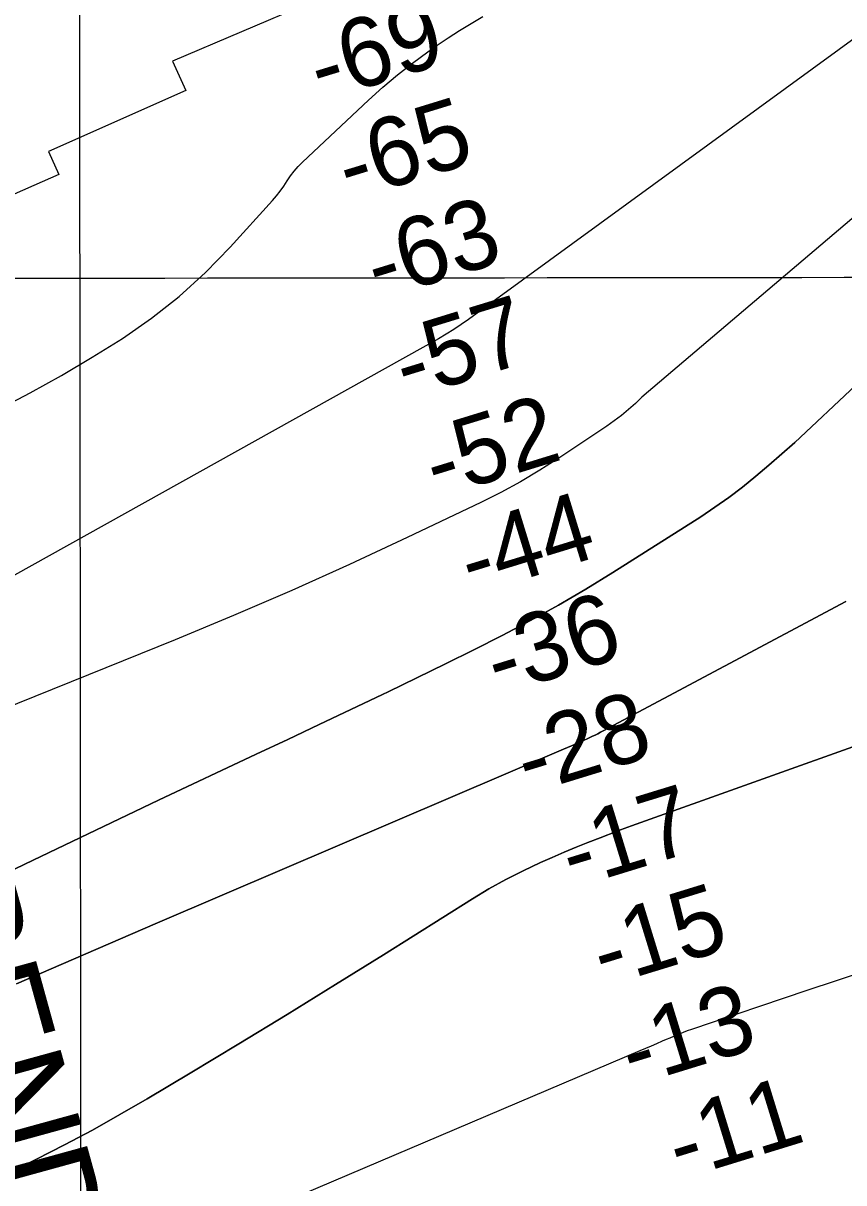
# Model space of a CAD drawing. Extents: x 3297753 to 3335611, y 652252 to 677623.
# Drawn here: x 3317590 to 3318384, y 659798 to 660921 of the extents above; entities that cross this region are included whole.
import ezdxf

# ---------------------------------------------------------------- set-up
doc = ezdxf.new("R2010")
doc.units = 0
for name, color, linetype in [('V-CHAN-NAID', 7, 'Continuous'), ('V-GRID-MAJR', 7, 'Continuous'), ('V-RIVR-EDGE', 7, 'Continuous'), ('V-RIVR-RANG', 7, 'Continuous'), ('V-RRAP-FSHR', 7, 'Continuous'), ('V-RRAP-RVMT', 7, 'Continuous'), ('V-TOPO-DPTH', 7, 'Continuous'), ('V-TOPO-MAJR', 7, 'Continuous'), ('V-TOPO-MINR', 7, 'Continuous')]:
    doc.layers.add(name, color=color, linetype=linetype)

msp = doc.modelspace()

# ---------------------------------------------------------------- linework, layer by layer
at = {"layer": 'V-GRID-MAJR'}
for points in [[(3317647.879, 657646.666), (3317644.7970000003, 660673.924), (3317638.625, 666735.341), (3317632.454, 672796.784), (3317629.365, 675830.954)], [(3301868.458, 660661.303), (3307127.238, 660664.745), (3312386.018, 660668.952), (3317644.7970000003, 660673.924), (3322903.575, 660679.66), (3328162.353, 660686.162), (3333421.129, 660693.428), (3333421.13, 660693.428)]]:
    msp.add_spline(points, degree=3, dxfattribs=at)
at = {"layer": 'V-RIVR-EDGE'}
msp.add_spline([(3319472.941637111, 662096.7930483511), (3319451.3588761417, 662084.8263787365), (3319431.435066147, 662073.2700910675), (3319412.763924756, 662065.4410623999), (3319386.63724047, 662059.7028894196), (3319355.1274208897, 662056.0504476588), (3319321.5328949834, 662047.4293521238), (3319286.6877502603, 662035.909960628), (3319261.790162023, 662024.3659716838), (3319253.9098886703, 662022.3130370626), (3319243.962332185, 662022.3376345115), (3319236.9110218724, 662020.2826501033), (3319220.298964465, 662007.0602372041), (3319214.062268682, 661999.2004617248), (3319197.881091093, 661992.6087282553), (3319174.651677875, 661985.2054549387), (3319135.249286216, 661974.5263003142), (3319095.8438198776, 661962.603701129), (3319061.8266133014, 661950.6677783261), (3319035.6896800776, 661940.7847901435), (3319017.017513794, 661932.5412799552), (3319004.1501385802, 661925.1123842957), (3318977.5966740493, 661914.4014579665), (3318949.3975821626, 661908.6684094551), (3318929.074664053, 661903.3303694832), (3318893.4067056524, 661894.2999168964), (3318836.1693099, 661878.6910544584), (3318802.1592775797, 661869.6565022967), (3318784.3232485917, 661864.3123129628), (3318761.0999847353, 661859.3959287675), (3318735.3744583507, 661848.2684711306), (3318707.1599930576, 661836.3181998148), (3318683.937754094, 661831.8162971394), (3318667.767850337, 661829.7838603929), (3318647.8604386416, 661824.8592770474), (3318612.1842810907, 661812.5129722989), (3318583.557384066, 661801.3926889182), (3318550.7836220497, 661789.4536914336), (3318517.189096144, 661780.8325958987), (3318486.906322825, 661770.5453751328), (3318459.104289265, 661757.7651158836), (3318437.1142210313, 661748.7008418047), (3318401.0928960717, 661732.5599758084), (3318376.26750918, 661719.6611275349), (3318350.3290856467, 661712.3999159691), (3318322.694633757, 661702.8889443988), (3318295.6167001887, 661690.5591544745), (3318275.8849717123, 661686.6635262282), (3318257.8395182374, 661681.0732629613), (3318243.7328864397, 661673.2193063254), (3318214.402406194, 661661.4585747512), (3318180.554292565, 661645.7645948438), (3318148.3966339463, 661630.066434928), (3318131.4656104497, 661619.4020199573), (3318111.1439235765, 661604.8015699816), (3318079.514916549, 661575.0148916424), (3318056.375804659, 661560.4214083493), (3318032.664847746, 661542.4484083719), (3318016.2987025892, 661532.346085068), (3317961.5347636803, 661489.6563784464), (3317862.7409676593, 661415.5201918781), (3317830.000317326, 661391.9346352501), (3317829.4284723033, 661388.5551185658), (3317827.160598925, 661382.925841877), (3317810.80142045, 661375.6409435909), (3317785.9690668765, 661359.9246703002), (3317761.132533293, 661342.5179419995), (3317743.6157314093, 661322.83916031), (3317726.093356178, 661300.9064386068), (3317708.570980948, 661278.9737169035), (3317696.7168958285, 661270.5507019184), (3317673.576390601, 661255.3937336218), (3317601.3165498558, 661201.4775203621), (3317560.671782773, 661171.7131354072), (3317529.070642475, 661153.1961571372), (3317513.8245006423, 661140.2736221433), (3317483.9026686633, 661117.2445838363), (3317464.1514334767, 661105.4601655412), (3317423.524779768, 661083.0210856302), (3317409.427901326, 661079.1115240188), (3317401.539111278, 661079.1310307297), (3317375.02187604, 661065.6728774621), (3317364.298940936, 661058.9375308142), (3317348.501854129, 661051.0877541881), (3317330.4591873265, 661046.6244609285), (3317307.322862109, 661033.1579476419), (3317289.2704419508, 661024.7502593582), (3317263.8829633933, 661012.4162894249), (3317240.770324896, 661008.5290211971), (3317230.0529631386, 661004.047614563), (3317228.3527547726, 661000.107399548), (3317221.5867547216, 660998.4336645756), (3317196.2118161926, 660991.1710596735), (3317170.2678193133, 660981.6559080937), (3317149.4105141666, 660978.3265515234), (3317103.1615504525, 660960.9727700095), (3317073.2689785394, 660949.7769167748), (3317034.3383531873, 660929.5875968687), (3316995.9726061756, 660909.9603686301), (3316948.0192540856, 660886.9759170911), (3316914.7401988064, 660873.5344838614), (3316885.9704168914, 660860.6453889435), (3316880.8879051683, 660856.1500489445), (3316871.2891533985, 660848.2849456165), (3316865.650123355, 660846.6084239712), (3316855.5073932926, 660846.6335040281), (3316850.436028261, 660846.6460440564), (3316844.222366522, 660840.4630357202), (3316839.713093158, 660839.9106974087), (3316835.7700914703, 660840.4839357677), (3316830.6889730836, 660836.5520807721), (3316818.8362813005, 660828.69255079), (3316813.7635229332, 660828.1416058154), (3316808.125886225, 660827.0285691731), (3316803.6180061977, 660827.0397158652), (3316796.8352861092, 660818.6041608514), (3316784.9798076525, 660809.6176608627), (3316774.8203575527, 660802.8809208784), (3316771.4227274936, 660796.127460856), (3316765.182592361, 660779.238237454), (3316755.5545805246, 660759.5399490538), (3316745.937715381, 660744.3495406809), (3316732.375061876, 660728.6054006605), (3316712.626613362, 660717.9479523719), (3316683.852651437, 660703.368402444), (3316676.521773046, 660701.1325758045), (3316664.6746546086, 660695.5269858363), (3316651.676879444, 660680.3449374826), (3316633.048434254, 660666.8672775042), (3316616.117410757, 660656.2028625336), (3316590.149727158, 660637.1084658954), (3316544.4238416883, 660603.4122259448), (3316509.995523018, 660580.9578193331), (3316472.7330592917, 660551.7485593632), (3316428.7101688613, 660523.1195044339), (3316390.324915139, 660495.6034861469), (3316363.7965332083, 660477.6374528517), (3316349.689901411, 660469.783496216), (3316341.225086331, 660464.7330312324), (3316335.0267512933, 660464.7483579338), (3316325.447506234, 660464.7720446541), (3316313.605961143, 660461.4203947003), (3316289.9284443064, 660456.9710348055), (3316257.21287403, 660443.5282082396), (3316237.472785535, 660436.2516699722), (3316207.013941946, 660423.9302400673), (3316177.1032566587, 660405.4090817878), (3316154.5332031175, 660393.0681451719), (3316131.949216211, 660375.0923585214), (3316110.5047393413, 660362.185150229), (3316095.268350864, 660353.2070102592), (3316080.0166356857, 660338.0305352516), (3316051.216200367, 660312.744770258), (3316013.9216899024, 660270.5753552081), (3315988.5035579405, 660245.8447151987), (3315960.258247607, 660217.1766468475), (3315939.932380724, 660200.8857418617), (3315925.8062422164, 660185.1429951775), (3315911.127765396, 660173.9095218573), (3315895.315351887, 660159.8614101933), (3315882.8838483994, 660145.8049385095), (3315867.6307398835, 660130.0649784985), (3315849.0106547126, 660119.968228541), (3315837.714481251, 660109.2898802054), (3315808.904292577, 660080.0597201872), (3315786.883790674, 660062.0825402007), (3315758.087535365, 660038.487230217), (3315733.80891344, 660018.825168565), (3315725.31623163, 660002.5050035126), (3315692.0065229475, 659976.6669002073), (3315659.8196042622, 659949.1355552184), (3315603.3596369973, 659904.1960885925), (3315571.1643582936, 659873.2838335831), (3315569.473903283, 659873.2880135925), (3315558.756541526, 659868.8066069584), (3315547.4729080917, 659863.1996236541), (3315527.70355953, 659844.0899003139), (3315506.252115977, 659828.365267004), (3315477.473974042, 659812.0952620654), (3315461.117582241, 659805.9373337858), (3315440.8014687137, 659793.5908238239), (3315429.5025085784, 659781.7855054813), (3315402.39670828, 659758.1860154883), (3315361.760301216, 659731.8025405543), (3315304.197050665, 659696.44510566), (3315255.6634935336, 659666.7002274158), (3315169.909272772, 659624.6506393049), (3315140.01252085, 659611.76433106), (3315123.6505557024, 659603.3524627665), (3315098.8209888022, 659588.7631594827), (3315044.633074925, 659551.1434245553), (3314989.866349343, 659507.3267479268), (3314954.285980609, 659474.7323979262), (3314933.969867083, 659462.3858879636), (3314926.0573903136, 659452.826149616), (3314915.8840068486, 659440.4545595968), (3314897.8106866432, 659423.5945962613), (3314866.750737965, 659396.0604645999), (3314844.7260560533, 659376.3928296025), (3314848.656517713, 659370.7482262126), (3314824.9511341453, 659355.0291662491), (3314801.817595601, 659342.6896229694), (3314762.319305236, 659320.8112413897), (3314730.157466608, 659303.4226264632), (3314710.9669297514, 659290.5098448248), (3314664.676165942, 659256.2515132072), (3314628.5615722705, 659235.4917416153), (3314603.161553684, 659218.0864066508), (3314584.5456485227, 659209.6801117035), (3314564.8194933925, 659208.0384234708), (3314555.7953733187, 659204.6798068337), (3314546.758713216, 659196.2498251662), (3314528.110761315, 659174.8833751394), (3314492.471872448, 659118.6226549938), (3314473.8183472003, 659095.0022649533), (3314450.6653019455, 659074.7739316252), (3314428.653160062, 659060.177661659), (3314423.004376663, 659054.5567449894), (3314416.2174765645, 659044.4307349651), (3314398.1441563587, 659027.5707716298), (3314375.555989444, 659007.9045299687), (3314366.533262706, 659005.1093983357), (3314353.566140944, 659002.3240200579), (3314347.3552658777, 658997.2679817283), (3314346.770880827, 658988.817100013), (3314351.264827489, 658983.1711032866), (3314350.679049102, 658974.1567365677), (3314342.759605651, 658961.7795732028), (3314329.21924553, 658955.0511932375), (3314311.714983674, 658940.4437765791), (3314309.9994486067, 658930.3052265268), (3314294.200968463, 658921.8919648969), (3314283.476640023, 658914.5931332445), (3314276.1248615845, 658903.9050315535), (3314272.7244448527, 658896.0246015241), (3314237.727067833, 658871.3176482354), (3314206.690805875, 658853.3627616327), (3314198.2329574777, 658851.1297216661), (3314192.0332291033, 658850.581563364), (3314180.188897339, 658846.1029434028), (3314172.27642057, 658836.5432050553), (3314164.3555837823, 658823.6025566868), (3314142.346228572, 658810.1332567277), (3314120.890605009, 658792.7181684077), (3314097.189401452, 658778.6895634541), (3314086.4594996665, 658769.1367917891), (3314082.4997779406, 658762.9482101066), (3314080.224937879, 658754.5015084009), (3314072.3250011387, 658750.0131350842), (3314036.7864324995, 658734.3233351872), (3314006.327588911, 658722.0019052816), (3313997.2978954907, 658716.3893486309), (3313939.7165315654, 658673.7066086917), (3313888.343256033, 658634.9529370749), (3313863.5011491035, 658615.29226876), (3313820.60522868, 658586.6604271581), (3313772.637943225, 658558.0411255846), (3313732.004322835, 658532.7846206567), (3313718.4597827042, 658524.3657856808), (3313711.127510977, 658521.5664740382), (3313702.6752359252, 658521.5873740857), (3313693.0890241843, 658518.7936357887), (3313674.475905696, 658511.5143108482), (3313646.823340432, 658494.6780342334), (3313626.498866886, 658478.9506142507), (3313619.7272934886, 658475.0229392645), (3313610.1215750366, 658464.3404109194), (3313605.0125899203, 658449.138855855), (3313597.1126531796, 658444.6504825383), (3313577.9151496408, 658428.9202758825), (3313554.7593177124, 658407.5649725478), (3313537.8046074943, 658387.3213125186), (3313525.3508106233, 658364.2490807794), (3313506.1115069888, 658331.6143240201), (3313489.716101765, 658309.6788156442)], degree=3, dxfattribs=at)
at = {"layer": 'V-RRAP-FSHR'}
msp.add_spline([(3320150.091, 662315.5710000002), (3320047.664, 662286.0730000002), (3319931.171, 662251.4420000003), (3319796.745, 662213.6190000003), (3319527.389, 662140.5510000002), (3319274.193, 662042.7370000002), (3319037.812, 661963.7270000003), (3318810.274, 661886.8160000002), (3318640.56, 661831.2630000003), (3318442.36, 661771.5080000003), (3318223.46, 661674.4170000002), (3318125.373, 661625.8860000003), (3317894.869, 661465.5510000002), (3317737.052, 661336.6740000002), (3317612.895, 661222.6820000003), (3317433.813, 661109.8930000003), (3317347.157, 661063.4030000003), (3317219.776, 661006.2670000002), (3317048.566, 660941.6820000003), (3316920.502, 660895.5560000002), (3316802.751, 660835.2480000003), (3316727.515, 660743.3250000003), (3316559.686, 660646.4110000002), (3316447.95, 660562.2680000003), (3316323.703, 660479.2110000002), (3316253.559, 660449.9440000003), (3316120.171, 660384.2440000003), (3315999.77, 660284.1680000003), (3315912.514, 660202.1160000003), (3315858.046, 660160.3560000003)], degree=3, dxfattribs=at)
at = {"layer": 'V-RRAP-RVMT'}
for p, q in [((3317867.681000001, 660940.8559999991), (3317734.397000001, 660883.861999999)), ((3317734.397000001, 660883.8619999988), (3317747.066000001, 660855.599999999)), ((3317747.066000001, 660855.599999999), (3317614.2440000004, 660796.6099999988)), ((3317614.2440000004, 660796.6099999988), (3317624.1510000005, 660774.3469999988)), ((3317624.151000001, 660774.3469999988), (3317488.889000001, 660714.4659999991))]:
    msp.add_line(p, q, dxfattribs=at)
at = {"layer": 'V-TOPO-DPTH'}
for points in [[(3318690.4369152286, 660847.7218774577), (3318336.3833433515, 660514.7170960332), (3318323.8654653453, 660503.8013998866), (3318311.287394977, 660492.9551176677), (3318298.669196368, 660482.1551114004), (3318285.814165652, 660471.6701739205), (3318272.6846056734, 660461.5575357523), (3318259.1432518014, 660452.0033465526), (3318245.327368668, 660442.8214566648), (3318160.3942056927, 660388.9060465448), (3318134.153281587, 660372.7712025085), (3318107.621227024, 660357.1473524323), (3318080.6524767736, 660342.2899932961), (3318053.3925960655, 660327.9436281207), (3318025.862913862, 660314.0848687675), (3317998.2651892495, 660300.364266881), (3317970.565401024, 660286.8509011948), (3317942.79757039, 660273.4756929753), (3317937.3821298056, 660270.8921431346), (3317906.845777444, 660256.3493747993), (3317876.296407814, 660241.8340506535), (3317845.727512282, 660227.3598927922), (3317815.145599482, 660212.9131791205), (3317720.8011404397, 660168.4231197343), (3317660.0235451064, 660139.5788206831), (3317599.341914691, 660110.5352818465), (3317538.8042316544, 660081.1928833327)], [(3317538.8042316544, 660081.1928833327), (3317599.341914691, 660110.5352818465), (3317660.0235451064, 660139.5788206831), (3317720.8011404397, 660168.4231197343), (3317815.145599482, 660212.9131791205), (3317845.727512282, 660227.3598927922), (3317876.296407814, 660241.8340506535), (3317906.845777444, 660256.3493747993), (3317937.3821298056, 660270.8921431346), (3317942.79757039, 660273.4756929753), (3317970.565401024, 660286.8509011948), (3317998.2651892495, 660300.364266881), (3318025.862913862, 660314.0848687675), (3318053.3925960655, 660327.9436281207), (3318080.6524767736, 660342.2899932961), (3318107.621227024, 660357.1473524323), (3318134.153281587, 660372.7712025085), (3318160.3942056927, 660388.9060465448), (3318245.327368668, 660442.8214566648), (3318259.1432518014, 660452.0033465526), (3318272.6846056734, 660461.5575357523), (3318285.814165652, 660471.6701739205), (3318298.669196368, 660482.1551114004), (3318311.287394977, 660492.9551176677), (3318323.8654653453, 660503.8013998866), (3318336.3833433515, 660514.7170960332), (3318690.4369152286, 660847.7218774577)], [(3318770.129470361, 660354.8802798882), (3318178.3031653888, 660143.4917256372), (3318174.811763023, 660142.2328137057), (3318171.325506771, 660140.9599376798), (3318167.8469696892, 660139.6661155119), (3318164.3735787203, 660138.3583292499), (3318147.9396136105, 660132.1141879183), (3318136.2910263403, 660127.5815163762), (3318124.6929777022, 660122.9257965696), (3318113.1707370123, 660118.085504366), (3318101.699034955, 660113.1221638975), (3318090.342785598, 660108.1007626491), (3318073.4223930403, 660100.1743196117), (3318056.756228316, 660091.769892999), (3318040.4714053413, 660082.6484910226), (3318024.440810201, 660073.0491054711), (3317938.323029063, 660018.8991758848), (3317891.8231521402, 659989.880950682), (3317845.193258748, 659961.0748004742), (3317798.3683406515, 659932.58676276), (3317751.413406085, 659904.3108000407), (3317709.648652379, 659879.3536558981), (3317683.313609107, 659864.0165105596), (3317656.7588734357, 659849.0804569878), (3317629.874599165, 659834.7460410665), (3317602.770632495, 659820.8127169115), (3317575.6011186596, 659806.9927393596)], [(3317575.6011186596, 659806.9927393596), (3317602.770632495, 659820.8127169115), (3317629.874599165, 659834.7460410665), (3317656.7588734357, 659849.0804569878), (3317683.313609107, 659864.0165105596), (3317709.648652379, 659879.3536558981), (3317751.413406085, 659904.3108000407), (3317798.3683406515, 659932.58676276), (3317845.193258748, 659961.0748004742), (3317891.8231521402, 659989.880950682), (3317938.323029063, 660018.8991758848), (3318024.440810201, 660073.0491054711), (3318040.4714053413, 660082.6484910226), (3318056.756228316, 660091.769892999), (3318073.4223930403, 660100.1743196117), (3318090.342785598, 660108.1007626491), (3318101.699034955, 660113.1221638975), (3318113.1707370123, 660118.085504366), (3318124.6929777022, 660122.9257965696), (3318136.2910263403, 660127.5815163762), (3318147.9396136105, 660132.1141879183), (3318164.3735787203, 660138.3583292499), (3318167.8469696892, 660139.6661155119), (3318171.325506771, 660140.9599376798), (3318174.811763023, 660142.2328137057), (3318178.3031653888, 660143.4917256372), (3318770.129470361, 660354.8802798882)], [(3318385.927129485, 660360.9597833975), (3318151.00184071, 660235.5286041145), (3318148.427380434, 660234.1779320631), (3318145.8402947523, 660232.8523467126), (3318143.234270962, 660231.5643914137), (3318140.615621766, 660230.3015228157), (3318137.9835102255, 660229.0661487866), (3318135.3460809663, 660227.8423341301), (3318132.7006751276, 660226.635858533), (3318130.0499515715, 660225.4409423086), (3318127.815532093, 660224.4425023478), (3318124.039656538, 660222.7660768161), (3318120.2585098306, 660221.1017043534), (3318116.469456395, 660219.4554114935), (3318112.675131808, 660217.8211717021), (3317784.5661164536, 660077.4305554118), (3317717.4857870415, 660048.6529547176), (3317650.4420886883, 660019.790486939), (3317583.453336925, 659990.8007185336)], [(3317583.453336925, 659990.8007185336), (3317650.4420886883, 660019.790486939), (3317717.4857870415, 660048.6529547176), (3317784.5661164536, 660077.4305554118), (3318112.675131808, 660217.8211717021), (3318116.469456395, 660219.4554114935), (3318120.2585098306, 660221.1017043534), (3318124.039656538, 660222.7660768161), (3318127.815532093, 660224.4425023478), (3318130.0499515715, 660225.4409423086), (3318132.7006751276, 660226.635858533), (3318135.3460809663, 660227.8423341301), (3318137.9835102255, 660229.0661487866), (3318140.615621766, 660230.3015228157), (3318143.234270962, 660231.5643914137), (3318145.8402947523, 660232.8523467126), (3318148.427380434, 660234.1779320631), (3318151.00184071, 660235.5286041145), (3318385.927129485, 660360.9597833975)]]:
    msp.add_lwpolyline(points, dxfattribs=at)
at = {"layer": 'V-TOPO-MAJR'}
msp.add_lwpolyline([(3318720.817692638, 661011.4595790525), (3318188.509325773, 660558.6403545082), (3318182.150746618, 660552.510837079), (3318175.5634786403, 660546.642379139), (3318168.7968627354, 660541.000081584), (3318161.7612249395, 660535.697024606), (3318154.5462392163, 660530.6201280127), (3318108.213597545, 660499.6928764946), (3318089.81858333, 660487.9796262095), (3318071.1142610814, 660476.810684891), (3318051.945976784, 660466.4582070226), (3318032.468384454, 660456.6500381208), (3317961.1691291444, 660422.6539129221), (3317905.584083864, 660396.7685561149), (3317849.699475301, 660371.5638561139), (3317793.365521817, 660347.3801413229), (3317736.7320050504, 660323.8770833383), (3317313.9280560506, 660152.9051854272)], dxfattribs=at)
at = {"layer": 'V-TOPO-MINR'}
for points in [[(3318685.700132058, 661119.0655922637), (3318020.7342811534, 660633.9725906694), (3318006.3907595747, 660624.243419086), (3317991.6088610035, 660615.1176558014), (3317976.350687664, 660606.7412162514), (3317398.843067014, 660284.8033257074)], [(3317566.084467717, 660546.9935531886), (3317596.620895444, 660563.0144221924), (3317626.800085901, 660579.6596750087), (3317656.4434204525, 660597.2415035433), (3317685.7295177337, 660615.4477158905), (3317713.8630060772, 660635.1665005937), (3317740.8345065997, 660656.25645121), (3317766.0630253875, 660679.4031506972), (3317790.129556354, 660703.9210160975), (3317830.9649583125, 660748.9463199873), (3317834.8341266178, 660753.4633604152), (3317838.523892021, 660758.1146232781), (3317841.9445530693, 660762.9672197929), (3317845.185811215, 660767.9540387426), (3317848.479412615, 660772.8895874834), (3317852.019801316, 660777.6245951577), (3317855.930370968, 660782.0587912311), (3317860.0877279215, 660786.2924462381), (3317924.0590603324, 660846.3729512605), (3317937.807865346, 660858.7484383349), (3317951.885799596, 660870.719867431), (3317966.457427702, 660882.0852095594), (3317981.3581850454, 660893.0464937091), (3317990.265983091, 660899.3130844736), (3318001.0685425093, 660906.6653528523), (3318012.01455699, 660913.7895677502), (3318023.1757540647, 660920.5717024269), (3318034.4804062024, 660927.1257836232)], [(3317538.8042316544, 660081.1928833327), (3317599.341914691, 660110.5352818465), (3317660.0235451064, 660139.5788206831), (3317720.8011404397, 660168.4231197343), (3317815.145599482, 660212.9131791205), (3317845.727512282, 660227.3598927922), (3317876.296407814, 660241.8340506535), (3317906.845777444, 660256.3493747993), (3317937.3821298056, 660270.8921431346), (3317942.79757039, 660273.4756929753), (3317970.565401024, 660286.8509011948), (3317998.2651892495, 660300.364266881), (3318025.862913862, 660314.0848687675), (3318053.3925960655, 660327.9436281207), (3318080.6524767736, 660342.2899932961), (3318107.621227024, 660357.1473524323), (3318134.153281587, 660372.7712025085), (3318160.3942056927, 660388.9060465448), (3318245.327368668, 660442.8214566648), (3318259.1432518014, 660452.0033465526), (3318272.6846056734, 660461.5575357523), (3318285.814165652, 660471.6701739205), (3318298.669196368, 660482.1551114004), (3318311.287394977, 660492.9551176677), (3318323.8654653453, 660503.8013998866), (3318336.3833433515, 660514.7170960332), (3318690.4369152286, 660847.7218774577)], [(3317575.6011186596, 659806.9927393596), (3317602.770632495, 659820.8127169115), (3317629.874599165, 659834.7460410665), (3317656.7588734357, 659849.0804569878), (3317683.313609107, 659864.0165105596), (3317709.648652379, 659879.3536558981), (3317751.413406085, 659904.3108000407), (3317798.3683406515, 659932.58676276), (3317845.193258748, 659961.0748004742), (3317891.8231521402, 659989.880950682), (3317938.323029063, 660018.8991758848), (3318024.440810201, 660073.0491054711), (3318040.4714053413, 660082.6484910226), (3318056.756228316, 660091.769892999), (3318073.4223930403, 660100.1743196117), (3318090.342785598, 660108.1007626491), (3318101.699034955, 660113.1221638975), (3318113.1707370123, 660118.085504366), (3318124.6929777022, 660122.9257965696), (3318136.2910263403, 660127.5815163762), (3318147.9396136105, 660132.1141879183), (3318164.3735787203, 660138.3583292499), (3318167.8469696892, 660139.6661155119), (3318171.325506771, 660140.9599376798), (3318174.811763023, 660142.2328137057), (3318178.3031653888, 660143.4917256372), (3318770.129470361, 660354.8802798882)], [(3317583.453336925, 659990.8007185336), (3317650.4420886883, 660019.790486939), (3317717.4857870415, 660048.6529547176), (3317784.5661164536, 660077.4305554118), (3318112.675131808, 660217.8211717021), (3318116.469456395, 660219.4554114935), (3318120.2585098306, 660221.1017043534), (3318124.039656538, 660222.7660768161), (3318127.815532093, 660224.4425023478), (3318130.0499515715, 660225.4409423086), (3318132.7006751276, 660226.635858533), (3318135.3460809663, 660227.8423341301), (3318137.9835102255, 660229.0661487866), (3318140.615621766, 660230.3015228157), (3318143.234270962, 660231.5643914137), (3318145.8402947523, 660232.8523467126), (3318148.427380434, 660234.1779320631), (3318151.00184071, 660235.5286041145), (3318385.927129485, 660360.9597833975)], [(3317859.8893251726, 659786.9375567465), (3318186.806793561, 659925.9846525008), (3318192.2265316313, 659928.3001613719), (3318197.641239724, 659930.6273218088), (3318203.048402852, 659932.971959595), (3318208.4505360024, 659935.3282489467), (3318212.265280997, 659936.9994933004), (3318215.7638836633, 659938.5106678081), (3318219.2726365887, 659939.9975396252), (3318222.7966149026, 659941.447957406), (3318226.330743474, 659942.8740724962), (3318231.102157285, 659944.7707642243), (3318233.425716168, 659945.6585230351), (3318235.7722395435, 659946.4836712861), (3318348.4789965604, 659984.4267706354), (3318406.0451254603, 660003.6930033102)]]:
    msp.add_lwpolyline(points, dxfattribs=at)

# ---------------------------------------------------------------- texts
at = {"layer": 'V-CHAN-NAID'}
msp.add_text('PLAQUEMINE BEND "213" (210.4)', height=100.00000199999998, rotation=285.40510731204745, dxfattribs=at).set_placement((3317236.489064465, 660963.8755117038))
at = {"layer": 'V-RIVR-RANG'}
for s, p in [('-69', (3317877.7116639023, 660844.8594887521)), ('-65', (3317905.1118179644, 660748.6636065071)), ('-63', (3317932.764092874, 660652.5452788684)), ('-57', (3317960.4163677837, 660556.4279512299)), ('-52', (3317989.5813677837, 660460.7749512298)), ('-44', (3318023.5366639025, 660366.5964887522)), ('-36', (3318048.9198511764, 660269.7801696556)), ('-28', (3318078.0838511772, 660174.1281696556)), ('-17', (3318121.367618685, 660082.8182276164)), ('-15', (3318151.5411020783, 659987.4764460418)), ('-13', (3318179.1933769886, 659891.3581184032)), ('-11', (3318224.746232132, 659800.7471678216))]:
    msp.add_text(s, height=67.00000000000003, rotation=17.09836111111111, dxfattribs=at).set_placement(p)

doc.saveas('drawing.dxf')
